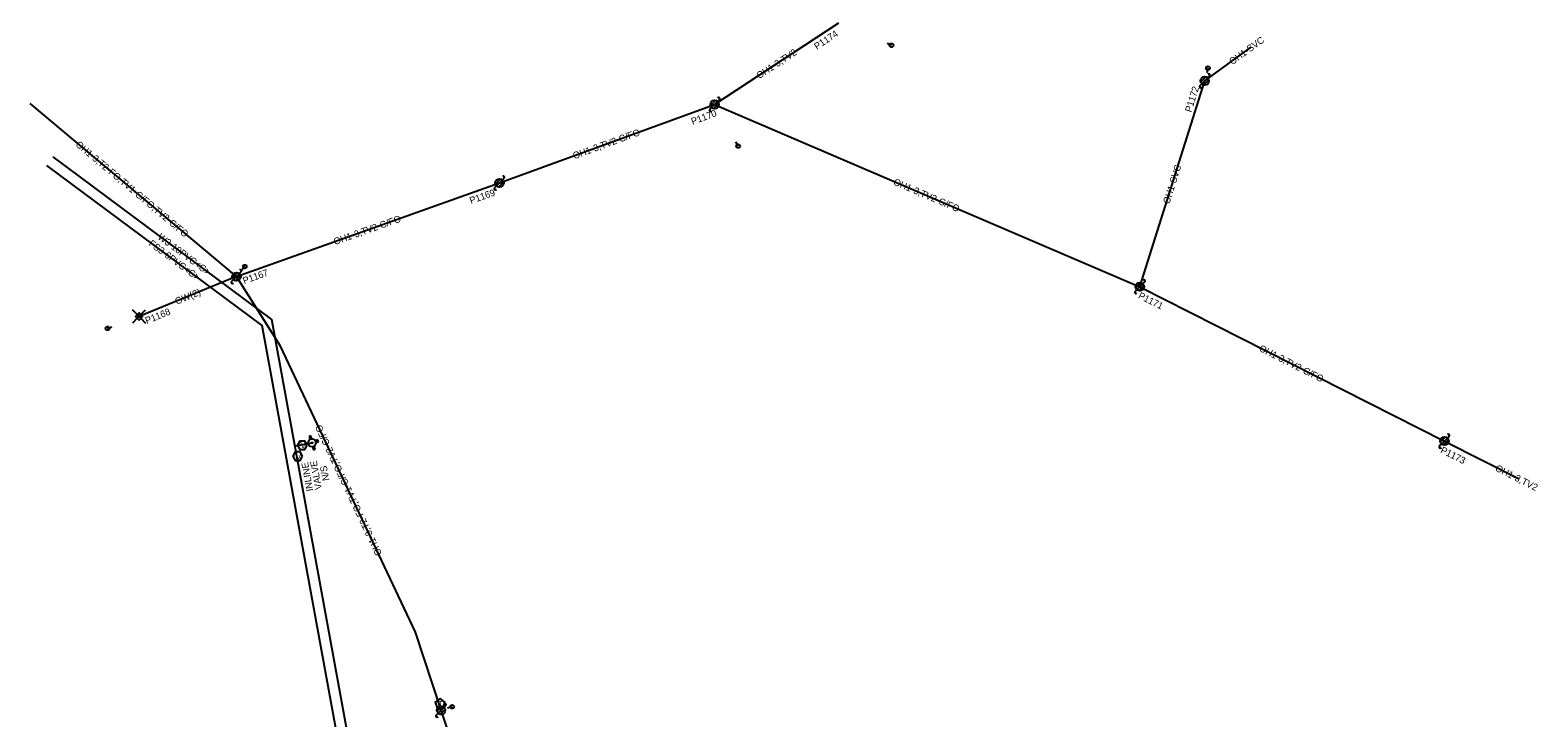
# Model space of a CAD drawing. Extents: x 2336688 to 2352634, y 362473 to 369571.
# Drawn here: x 2346209 to 2347096, y 368647 to 369052 of the extents above; entities that cross this region are included whole.
import ezdxf

# ---------------------------------------------------------------- set-up
doc = ezdxf.new("R2010")
doc.units = 0
for name, color, linetype in [('RD_EX_DV_TX_Prop', 7, 'Continuous'), ('RD_EX_RW_TX', 7, 'Continuous'), ('RD_HC_Data_Tic', 7, 'Continuous'), ('RD_PD_CstnLmt', 7, 'Continuous'), ('RD_PD_PatLn4', 7, 'Continuous'), ('RD_SHT_ShtClip', 7, 'Continuous'), ('RD_Sketch1', 7, 'Continuous'), ('RD_Sketch2', 7, 'Continuous'), ('RD_Sketch5', 7, 'Continuous')]:
    doc.layers.add(name, color=color, linetype=linetype)

# ---------------------------------------------------------------- blocks, each defined once
blk = doc.blocks.new('GW')
at = {"layer": 'RD_HC_Data_Tic'}
blk.add_line((0, 0), (0, 5), dxfattribs=at)
blk.add_circle((0, 0), 2, dxfattribs=at)

msp = doc.modelspace()

# ---------------------------------------------------------------- linework, layer by layer
at = {"layer": 'RD_EX_RW_TX'}
msp.add_lwpolyline([(2346450.33, 368658.69), (2346447.48, 368656.62), (2346448.57, 368653.27), (2346452.1, 368653.27), (2346453.19, 368656.62)], close=True, dxfattribs=at)
at = {"layer": 'RD_HC_Data_Tic'}
for p, q in [((2346897.46, 369021.14), (2346900.52, 369024.21)), ((2346901.64, 369023.56), (2346902.7, 369024.62)), ((2346897.05, 369018.96), (2346898.11, 369020.02)), ((2346898.11, 369020.02), (2346901.64, 369023.56)), ((2346899.23, 369019.38), (2346902.29, 369022.44)), ((2346609.36, 369007.31), (2346612.42, 369010.38)), ((2346610, 369006.19), (2346613.54, 369009.73)), ((2346611.12, 369005.55), (2346614.19, 369008.61)), ((2346613.54, 369009.73), (2346614.6, 369010.79)), ((2346608.94, 369005.13), (2346610, 369006.19)), ((2346482.83, 368961.15), (2346485.89, 368964.21)), ((2346483.47, 368960.03), (2346487.01, 368963.57)), ((2346484.59, 368959.39), (2346487.66, 368962.45)), ((2346487.01, 368963.57), (2346488.07, 368964.63)), ((2346482.41, 368958.97), (2346483.47, 368960.03)), ((2346328.18, 368906.08), (2346331.24, 368909.15)), ((2346332.36, 368908.5), (2346333.42, 368909.56)), ((2346327.77, 368903.9), (2346328.83, 368904.96)), ((2346328.83, 368904.96), (2346332.36, 368908.5)), ((2346329.95, 368904.32), (2346333.01, 368907.38)), ((2346859.37, 368900.18), (2346862.43, 368903.24)), ((2346860.01, 368899.06), (2346863.55, 368902.6)), ((2346861.13, 368898.42), (2346864.2, 368901.48)), ((2346863.55, 368902.6), (2346864.61, 368903.66)), ((2346858.95, 368898), (2346860.01, 368899.06)), ((2346272.23, 368882.3), (2346269.4, 368879.47)), ((2346272.28, 368884.4), (2346269.45, 368887.23)), ((2346274.36, 368884.46), (2346277.2, 368887.3)), ((2346274.4, 368882.28), (2346277.23, 368879.45)), ((2347038.41, 368809.43), (2347041.47, 368812.49)), ((2347039.06, 368808.31), (2347042.59, 368811.84)), ((2347042.59, 368811.84), (2347043.66, 368812.9)), ((2347038, 368807.25), (2347039.06, 368808.31)), ((2347040.18, 368807.66), (2347043.24, 368810.72)), ((2346448.49, 368651.16), (2346451.55, 368654.22)), ((2346449.14, 368650.04), (2346452.67, 368653.57)), ((2346450.26, 368649.39), (2346453.32, 368652.45)), ((2346452.67, 368653.57), (2346453.74, 368654.63)), ((2346448.08, 368648.98), (2346449.14, 368650.04))]:
    msp.add_line(p, q, dxfattribs=at)
for points in [[(2346273.34, 368881.22), (2346275.46, 368883.34), (2346273.34, 368885.46), (2346271.22, 368883.34)], [(2346273.34, 368882.63), (2346274.05, 368883.34), (2346273.34, 368884.05), (2346272.63, 368883.34)]]:
    msp.add_lwpolyline(points, close=True, dxfattribs=at)
for centre in [(2346899.88, 369021.79), (2346611.77, 369007.96), (2346485.24, 368961.8), (2346330.6, 368906.73), (2346861.78, 368900.83), (2347040.83, 368810.08), (2346450.91, 368651.81)]:
    msp.add_circle(centre, 2.5, dxfattribs=at)
for centre, start, end in [((2346902.17, 369025.15), 315, 135), ((2346897.58, 369018.43), 135, 315), ((2346614.07, 369011.32), 315, 135), ((2346609.47, 369004.6), 135, 315), ((2346487.54, 368965.16), 315, 135), ((2346482.94, 368958.44), 135, 315), ((2346332.89, 368910.09), 315, 135), ((2346328.3, 368903.37), 135, 315), ((2346864.08, 368904.19), 315, 135), ((2346859.48, 368897.47), 135, 315), ((2347043.13, 368813.43), 315, 135), ((2347038.53, 368806.72), 135, 315), ((2346453.21, 368655.16), 315, 135), ((2346448.61, 368648.45), 135, 315)]:
    msp.add_arc(centre, 0.75, start, end, dxfattribs=at)
at = {"layer": 'RD_SHT_ShtClip'}
for p, q in [((2346611.77, 369007.96), (2346684.81, 369055.93)), ((2346899.88, 369021.79), (2346927.47, 369041.72)), ((2346861.78, 368900.83), (2346899.88, 369021.79)), ((2346330.6, 368906.73), (2346209.32, 369008.5)), ((2346485.24, 368961.8), (2346611.77, 369007.96)), ((2346611.77, 369007.96), (2346861.78, 368900.83)), ((2346330.6, 368906.73), (2346485.24, 368961.8)), ((2346330.6, 368906.73), (2346273.34, 368883.34)), ((2346861.78, 368900.83), (2347040.83, 368810.08)), ((2347040.83, 368810.08), (2347084.78, 368787.8)), ((2346484.5, 368553.72), (2346450.91, 368651.81))]:
    msp.add_line(p, q, dxfattribs=at)
msp.add_lwpolyline([(2346450.91, 368651.81), (2346435.82, 368697.76), (2346356.48, 368865.87), (2346330.6, 368906.73)], dxfattribs=at)
at = {"layer": 'RD_Sketch2'}
for p, q in [((2346374.41, 368813.06), (2346373.32, 368812.7)), ((2346373.32, 368812.7), (2346373.87, 368811.03)), ((2346374.98, 368811.35), (2346374.41, 368813.06)), ((2346365.06, 368807.22), (2346375.04, 368809.04)), ((2346375.28, 368806.74), (2346375.85, 368805.02)), ((2346375.85, 368805.02), (2346376.95, 368805.38)), ((2346376.95, 368805.38), (2346376.37, 368807.15)), ((2346378.41, 368810.71), (2346377.01, 368810.25)), ((2346377.35, 368809.14), (2346378.77, 368809.61)), ((2346378.77, 368809.61), (2346378.41, 368810.71))]:
    msp.add_line(p, q, dxfattribs=at)
msp.add_lwpolyline([(2346416.61, 368524.92), (2346351.49, 368881.57), (2346222.86, 368977.1)], dxfattribs=at)
for points in [[(2346369.53, 368801.21), (2346368.09, 368803.71), (2346365.2, 368803.71), (2346363.76, 368801.21), (2346365.2, 368798.71), (2346368.09, 368798.71)], [(2346372.24, 368807.59), (2346370.8, 368810.09), (2346367.91, 368810.09), (2346366.47, 368807.59), (2346367.91, 368805.09), (2346370.8, 368805.09)]]:
    msp.add_lwpolyline(points, close=True, dxfattribs=at)
for radius in [2.31, 0.289]:
    msp.add_circle((2346375.04, 368809.04), radius, dxfattribs=at)
for start, end in [(91.60125, 120.57757), (275.94754, 304.92386), (2.50808, 31.47532)]:
    msp.add_arc((2346375.04, 368809.04), 2.31, start, end, dxfattribs=at)
at = {"layer": 'RD_Sketch5'}
msp.add_lwpolyline([(2346410.56, 368523.52), (2346345.82, 368878.04), (2346219.16, 368972.12)], dxfattribs=at)

# ---------------------------------------------------------------- block references
at = {"layer": 'RD_HC_Data_Tic'}
for p, xscale, yscale, rotation in [((2346715.73, 369042.72), 0.5546771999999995, 0.5546771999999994, 66.670837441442), ((2346901.81, 369029.3), 0.5546771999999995, 0.5546771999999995, 166.0306567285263), ((2346625.6, 368983.48), 0.5546771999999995, 0.5546771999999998, 29.213219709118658), ((2346335.58, 368912.64), 0.5546771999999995, 0.5546771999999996, 139.99168577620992), ((2346254.82, 368876.31), 0.5546771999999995, 0.5546771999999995, -69.06650101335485), ((2346457.42, 368653.89), 0.5546771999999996, 0.5546771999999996, 107.257468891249)]:
    msp.add_blockref('GW', p, dxfattribs=dict(at, xscale=xscale, yscale=yscale, rotation=rotation))

# ---------------------------------------------------------------- texts
at = {"layer": 'RD_EX_DV_TX_Prop'}
for s, rotation, p in [('P1174', 33.29889, (2346671.86, 369039.95)), ('P1172', 72.51933, (2346891.98, 369003.06)), ('P1170', 20.04297, (2346598.8, 368995.93)), ('P1169', 19.60046, (2346468.51, 368949.4)), ('P1167', 19.60046, (2346335.17, 368902.3)), ('P1171', 333.12055, (2346860.39, 368894.28)), ('P1168', 22.22252, (2346277.91, 368878.82)), ('P1173', 333.12055, (2347038.14, 368803.42))]:
    msp.add_text(s, height=4, rotation=rotation, dxfattribs=at).set_placement(p)
at = {"layer": 'RD_EX_RW_TX'}
msp.add_text('T', height=3.75, dxfattribs=at).set_placement((2346449.11, 368653.47))
at = {"layer": 'RD_PD_CstnLmt'}
for s, rotation, p in [('W3-10PVC<C>', 323.39726, (2346283.98, 368929.22)), ('INLINE', 100.34783, (2346375.77, 368780.95)), ('VALVE', 100.34783, (2346380.89, 368781.89)), ('N/S', 100.34783, (2346385.24, 368787.08))]:
    msp.add_text(s, height=4, rotation=rotation, dxfattribs=at).set_placement(p)
at = {"layer": 'RD_PD_PatLn4'}
for s, rotation, p in [('OH1-SVC', 35.83772, (2346916.08, 369031.03)), ('OH1-3,TV2', 33.29889, (2346637.91, 369022.74)), ('OH1-3,TV2-C/FO', 20.04297, (2346529.23, 368975.72)), ('OH1-3,T2-FO,TV1-C/FO,TV2-C/FO', 319.99768, (2346235.65, 368983.8)), ('OH1-SVC', 72.51933, (2346879.09, 368949.14)), ('OH1-3,TV2-C/FO', 336.80454, (2346716.46, 368960.93)), ('OH1-3,TV2-C/FO', 19.60046, (2346388.57, 368925.25)), ('GW(2)', 22.22252, (2346295.46, 368890.22)), ('OH1-3,TV2-C/FO', 333.12055, (2346931.45, 368863.28)), ('OH1-3,T2-FO,TV1-C/FO,TV2-C/FO', 115.26464, (2346416.29, 368743.81)), ('OH1-3,TV2', 333.12055, (2347070.35, 368792.87))]:
    msp.add_text(s, height=4, rotation=rotation, dxfattribs=at).set_placement(p)
at = {"layer": 'RD_Sketch1'}
msp.add_text('FS3-6PVC<C>', height=4, rotation=323.39726, dxfattribs=at).set_placement((2346278.64, 368925.45))
at = {"layer": 'RD_Sketch2'}
for p in [(2346365.43, 368799.33), (2346368.14, 368805.71)]:
    msp.add_text('V', height=3.75, dxfattribs=at).set_placement(p)

doc.saveas('drawing.dxf')
